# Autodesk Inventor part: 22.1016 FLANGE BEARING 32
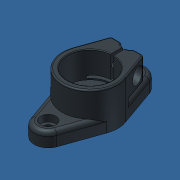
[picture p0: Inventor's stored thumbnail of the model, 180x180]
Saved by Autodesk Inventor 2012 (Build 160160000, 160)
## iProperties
Created: 2008-12
Part Number: 22.1016 FLANGE BEARING 32
Document SubType Name: Modeling
Designer: Oster
Density: 1.06 g/cm^3
Material: ABS Plastic
Mass: 25.0307 g
Surface Area: 130.147 cm^2
Volume: 23.6139 cm^3
Description: Flanschlager 32 Einzelteil
Material: ABS Plastik
Bezeichnung: Flanschlager 32 Einzelteil
Artikelnr: 221016/1
Lieferantennr: 72401
Zeichnungsnr: 22-1016-1FZ.000
MiniTec_ID: 221016/1
Teileart: K
Lieferant: MiniTec
Title: Flanschlager 32 Einzelteil
Author: Oster
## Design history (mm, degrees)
feature "Basis1"
node "Volumenkörpern"
node "Oberflächenkörpern"
node "Volumenkörper1"
other parameters: "Länge" = 1 [user parameter], "Breite" = 1 [user parameter], "Dicke_ø" = 1 [user parameter]
